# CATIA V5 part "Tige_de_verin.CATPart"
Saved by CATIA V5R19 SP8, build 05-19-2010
Part number: Tige de verin
Revision: ANY
Definition: UNKNOWN
Nomenclature: Tige de vérin
Source: Unknown
Bounding box of the stored display mesh (mm): x -3 to 3, y -3 to 3, z 0 to 150
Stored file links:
  D:\Documents\1_Travail\1 - ac-limoges.fr\OneDrive - ac-limoges.fr\STI2D_Turgot\2 -2I2D\3_SEQUENCE_Serre_Connectée\3- Spécificités\ITEC\EC 3 Ouverture automatique\Simulation  Ouverture Automatique\Tige_de_verin.CATPart
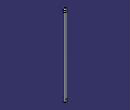
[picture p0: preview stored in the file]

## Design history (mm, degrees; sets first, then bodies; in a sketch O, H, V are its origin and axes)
Body1 "NONE" (main body)
  Solid1: solid without history
  Split1: SplitPlane face of Solid1
  Sketch1 on face of Split1, origin (0, 0, 145), H (1, 0, 0), V (0, 1, 0)
    projected circle E1 centre (0, 0) radius 3 from face of Split1
  Pad1: profile Sketch1, direction (0, 0, 1), length 5
  Fillet1: radius 1.5, on edge [face of Pad1 from Sketch1.E1 | end face of Pad1]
